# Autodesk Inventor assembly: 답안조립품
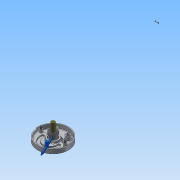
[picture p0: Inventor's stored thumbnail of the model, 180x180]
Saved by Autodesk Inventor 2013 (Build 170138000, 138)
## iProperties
Created: 2015-04
Part Number: 답안조립품
Document SubType Name: Assembly
Designer: Administrator
Author: Administrator
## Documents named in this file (10)
- C:\Users\ADMINI~1\AppData\Local\Temp\BNZ.553b3987d615aa\답안조립품.iam
- C:\Users\Administrator\Desktop\450406V1003\본체.ipt
- C:\Users\Administrator\Desktop\450406V1003\M 10 x 35.ipt
- C:\Users\Administrator\Desktop\450406V1003\덮개.ipt
- C:\Users\Administrator\Desktop\450406V1003\멈춤링.ipt
- C:\Users\Administrator\Desktop\450406V1003\베어링62_22.ipt
- C:\Users\Administrator\Desktop\450406V1003\슬라이더.ipt
- C:\Users\Administrator\Desktop\450406V1003\슬라이더2.ipt
- C:\Users\Administrator\Desktop\450406V1003\축.ipt
- C:\Users\Administrator\Desktop\450406V1003\평행핀.ipt
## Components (2 placed, 1 different names)
1. M 10 x 35:1
2. M 10 x 35:2
